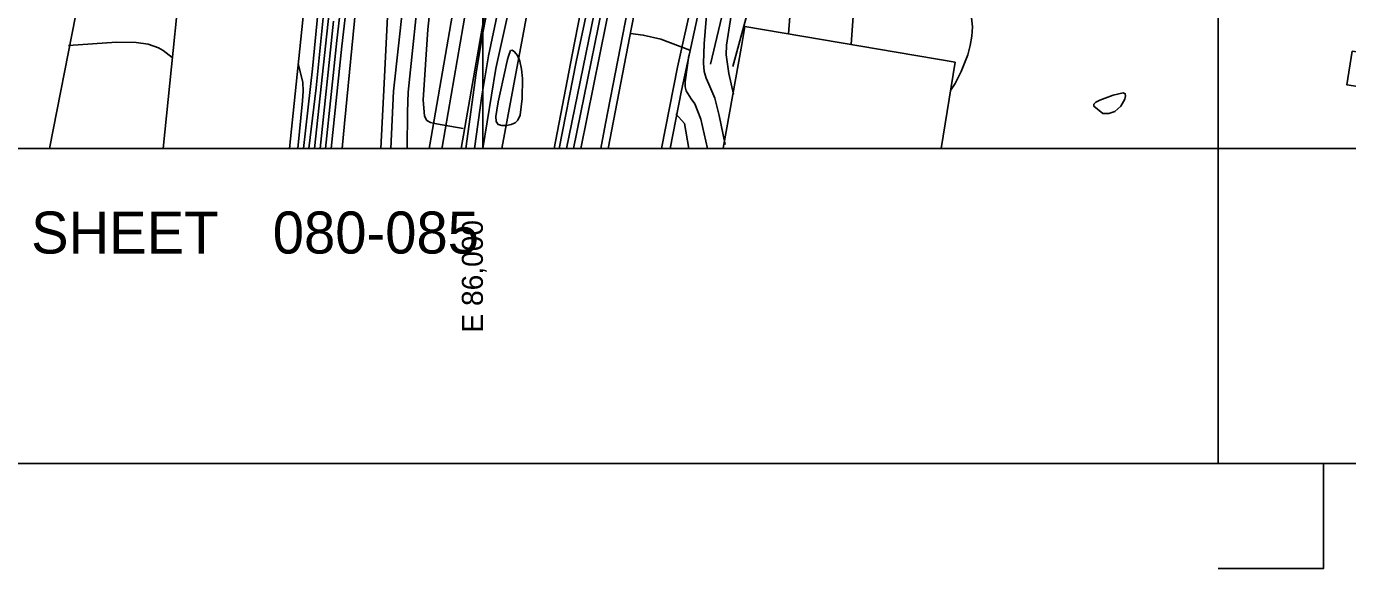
# Model space of a CAD drawing. Extents: x 79600 to 91800, y 75600 to 84400.
# Drawn here: x 85566 to 86823, y 75600 to 76116 of the extents above; entities that cross this region are included whole.
import ezdxf

# ---------------------------------------------------------------- set-up
doc = ezdxf.new("R2010")
doc.units = 0
for name, color, linetype in [('080-085$0$TI_BORDER', 7, 'Continuous'), ('080-085$0$TI_SHEET', 7, 'Continuous'), ('080-090$0$BLDG', 7, 'Continuous'), ('080-090$0$BRIDGE', 7, 'Continuous'), ('080-090$0$GRID', 7, 'Continuous'), ('080-090$0$INDEX', 7, 'Continuous'), ('080-090$0$INTER', 7, 'Continuous'), ('080-090$0$INTERSTATE', 7, 'Continuous'), ('080-090$0$ROAD', 7, 'Continuous'), ('080-090$0$TI_BORDER', 7, 'Continuous'), ('080-090$0$WALL', 7, 'Continuous')]:
    doc.layers.add(name, color=color, linetype=linetype)

msp = doc.modelspace()

# ---------------------------------------------------------------- linework, layer by layer
at = {"layer": '080-085$0$TI_BORDER'}
msp.add_lwpolyline([(79700, 80300), (86700, 80300), (86700, 75700), (79700, 75700)], close=True, dxfattribs=at)
at = {"layer": '080-085$0$TI_SHEET'}
msp.add_lwpolyline([(86800, 75700), (86800, 75600), (86700, 75600)], dxfattribs=at)
at = {"layer": '080-090$0$BLDG'}
for points in [[(85695.6, 76000), (85718.1, 76221.3), (85837.4, 76208.4), (85815.9, 76000)], [(85358.1, 76000), (85392.2, 76170.4), (85612.5, 76127.6), (85587.5, 76000)], [(86228.7, 76000.3), (86246.5, 76099.1), (86249.4, 76116.2), (86449.4, 76082.2), (86436.3, 76000)]]:
    msp.add_lwpolyline(points, dxfattribs=at)
msp.add_lwpolyline([(86827.4, 76092.8), (86867, 76086.7), (86862.1, 76054.6), (86822.5, 76060.6)], close=True, dxfattribs=at)
at = {"layer": '080-090$0$BRIDGE'}
for p, q in [((86145.8, 76172.8), (86116.8, 76023.7)), ((86209.4, 76148.7), (86188.9, 76055.3)), ((86188.9, 76055.3), (86178.3, 76000)), ((86116.8, 76023.7), (86112.2, 76000))]:
    msp.add_line(p, q, dxfattribs=at)
at = {"layer": '080-090$0$GRID'}
for p, q in [((86000, 80000), (86000, 76000)), ((90000, 76000), (85000, 76000))]:
    msp.add_line(p, q, dxfattribs=at)
at = {"layer": '080-090$0$INDEX'}
for points in [[(85927.8, 76000), (85928.3, 76034.8), (85929, 76053.7), (85940.5, 76166.4), (85942.9, 76204.7), (85944, 76214.5), (85946, 76224.2), (85952.3, 76242.8), (85964.5, 76269.2), (85970.7, 76287.2), (85974.6, 76305.9), (85979.2, 76352.9), (85985.2, 76393.6), (85995.7, 76517.2), (85998, 76546), (86001.9, 76573.1), (86010.6, 76615.9), (86033, 76705.4), (86037, 76723.4), (86038.8, 76748.9)], [(86093.2, 76000), (86135.3, 76209.3), (86140.8, 76236), (86143.9, 76254.4), (86147.6, 76303), (86150.1, 76322.3), (86178.9, 76480.4), (86187.7, 76517), (86195.1, 76545.1), (86212.3, 76599.8), (86215.3, 76608.6), (86218.8, 76616.1), (86223.1, 76621.8), (86233.7, 76630.3)], [(86230.7, 76003.8), (86225, 76031.4), (86220.7, 76047.9), (86215.2, 76061.3), (86212.6, 76067), (86210.7, 76073.4), (86209.9, 76081.2), (86210.7, 76099.7), (86213.9, 76138.6), (86216.4, 76157.4), (86223.2, 76185.1), (86231.3, 76213.4), (86243.4, 76250.4), (86253.2, 76278), (86269, 76313.3), (86276.5, 76331.1), (86282.5, 76349.4), (86292, 76393.6)], [(85991.9, 76000), (85999, 76050.2), (86005.5, 76088.4), (86029.4, 76202.5)], [(85839.7, 76000), (85860.2, 76189.1)]]:
    msp.add_lwpolyline(points, dxfattribs=at)
at = {"layer": '080-090$0$INTER'}
msp.add_line((85699.1, 76000), (85699.1, 76000), dxfattribs=at)
for points in [[(86136.6, 76835.2), (86135.6, 76809.7), (86134.3, 76791.6), (86112.5, 76652.2), (86066.7, 76407.8), (86054.2, 76342.6), (86048.2, 76314.1), (86025.3, 76231.1), (86017.9, 76203.3), (86000.1, 76110.1), (85993.6, 76072.1), (85983.9, 76000)], [(86238.3, 76654.5), (86225.3, 76647.6), (86213.2, 76641.1), (86207.8, 76637.2), (86203.4, 76632.2), (86200, 76625.5), (86190.7, 76590.4), (86167.9, 76488.3), (86139.6, 76349.9), (86130.4, 76304.6), (86128.6, 76296.7), (86126, 76290.4), (86121.8, 76286.9), (86115.6, 76287.2), (86108, 76290.3), (86100.1, 76295.3), (86092.7, 76300.9), (86086.3, 76307.1), (86072.9, 76326.3), (86070.1, 76328.1), (86067.7, 76324.9), (86018.7, 76104.6), (86012.3, 76076.2), (86000.1, 76000)], [(86237.2, 76648.5), (86227.4, 76643.3), (86217.1, 76637.7), (86212, 76634), (86207.6, 76629), (86204.2, 76622.3), (86194.3, 76587.4), (86174.3, 76502.5), (86128.4, 76268.5), (86088.7, 76082.6), (86072.7, 76000)], [(86079.6, 76000), (86126.9, 76231.2), (86138.9, 76305), (86170.5, 76470.3), (86178.4, 76506.3), (86194, 76569.5), (86201.3, 76596.9), (86205.9, 76613), (86208.3, 76619.8), (86211.5, 76625.6), (86215.8, 76630.2), (86236, 76642.5)], [(86086.4, 76000), (86123.3, 76182.4), (86133, 76229.4), (86138.5, 76258.2), (86142.8, 76296.9), (86146.7, 76325.7), (86174.8, 76474.7), (86180.6, 76501.8), (86192.3, 76548.3), (86208.1, 76602.5), (86210.9, 76611.2), (86214.6, 76618.8), (86219.2, 76624.9), (86234.8, 76636.5)], [(85912.3, 76000), (85915, 76054.5), (85928.3, 76175.7), (85929.8, 76194.7), (85931.7, 76213.9), (85933.5, 76223.3), (85936.3, 76232.4), (85944.4, 76249.5), (85954.4, 76265.6), (85959.2, 76273.9), (85963.3, 76282.6), (85966.5, 76291.6), (85970.6, 76310.1), (85973.5, 76347.2), (85979.8, 76389.5), (85983.3, 76419.8), (85989.9, 76518.4), (85991.3, 76537.6), (85993.4, 76556.3), (85996, 76571.5)], [(85981.1, 76019.2), (85955.8, 76023.5), (85950.3, 76024.7), (85946.6, 76026.8), (85944.4, 76030.9), (85943.2, 76046.5), (85947.6, 76113.2), (85953.6, 76170.7), (85955.1, 76199.6), (85956.6, 76218.8), (85960.5, 76237.7), (85969.7, 76265.2), (85975.2, 76283.7), (85979, 76303), (85991.2, 76403.1), (85992.3, 76414.8)], [(85834.5, 76000), (85841.2, 76057.7), (85852.6, 76172.5), (85854.4, 76191.5), (85855.5, 76208.9), (85855.4, 76215.6), (85854.4, 76220.2), (85852.1, 76223.1), (85847.9, 76224.8), (85805.9, 76228.5), (85767.4, 76233.9), (85720.1, 76239.3), (85686.8, 76238.6), (85681.3, 76238.4), (85673.4, 76239.8), (85670, 76241.9), (85666.9, 76245.5), (85664.7, 76250.8), (85663.5, 76258), (85663.3, 76266.5), (85664.2, 76275.4), (85671.2, 76300.1)], [(85829.3, 76000), (85837.9, 76075.8), (85846.6, 76168.3), (85848.1, 76186.6), (85848.5, 76194.9), (85848.3, 76201.7), (85847.4, 76206.1), (85845.5, 76207.7), (85837.1, 76205.2)], [(85855.5, 76000), (85865.9, 76097.4), (85871.1, 76144.1)], [(86290.8, 76109.2), (86294.1, 76149.9)], [(85850.2, 76000), (85861.1, 76102.7), (85865.4, 76141.5)], [(86352.9, 76130.6), (86350.7, 76099)], [(85845, 76000), (85857.8, 76121.3)], [(86238.7, 76051.8), (86234.2, 76071.3), (86231.6, 76089.1), (86231.9, 76098.5), (86236.4, 76126.9)], [(86445.1, 76055.1), (86449.6, 76062), (86455.3, 76073.2), (86461.5, 76089.3), (86463.9, 76098.1), (86465.4, 76107), (86465.9, 76115.8), (86465.2, 76124.3)], [(86140.5, 76109.5), (86152.6, 76108), (86169.4, 76104.2), (86197, 76093.5)], [(85704.4, 76086.6), (85695.8, 76093.3), (85691.4, 76096), (85681.4, 76099.3), (85670.1, 76100.9), (85651.4, 76101.3), (85605.6, 76098.1)], [(85823.8, 76000), (85828.3, 76045.4), (85828.8, 76054.6), (85828.6, 76062.8), (85824.2, 76080.9)], [(86195.9, 76088.6), (86192.7, 76063.4), (86192.6, 76058.8), (86193.4, 76054.9), (86198.4, 76047.4), (86201.7, 76042.4), (86207.4, 76028.1), (86213.9, 76000)], [(86196.1, 76000), (86192, 76023.8), (86183.6, 76033.1)]]:
    msp.add_lwpolyline(points, dxfattribs=at)
for points in [[(86023.5, 76084.7), (86016.4, 76053), (86014.7, 76044.3), (86013.3, 76036.6), (86012.4, 76030.4), (86012.7, 76025.8), (86014.4, 76023), (86017.9, 76021.8), (86022.4, 76021.9), (86026.9, 76022.8), (86030.6, 76024.4), (86033.4, 76027.1), (86035.4, 76031.7), (86037.5, 76047.6), (86037.6, 76066.8), (86036.8, 76075.6), (86035.3, 76083.1), (86032.9, 76088.6), (86030.2, 76092.1), (86027.9, 76093.6), (86026.3, 76093.3), (86024.3, 76087.9)], [(86591.2, 76033.3), (86595.7, 76033.4), (86601.6, 76035.4), (86607.2, 76040.3), (86611.1, 76047.1), (86611.8, 76050.1), (86611.4, 76052.1), (86609.5, 76052.9), (86599.8, 76050.8), (86587.3, 76046), (86583.4, 76044), (86581.6, 76042.1), (86581.6, 76040.3), (86590.1, 76033.4)]]:
    msp.add_lwpolyline(points, close=True, dxfattribs=at)
at = {"layer": '080-090$0$INTERSTATE'}
for p, q in [((86077.3, 76315.9), (86018, 76000)), ((86141.4, 76115.1), (86170, 76261.2)), ((85915.2, 76240.8), (85905.5, 76049.4)), ((86108, 76209.5), (86085.1, 76089.3)), ((85880.1, 76144.6), (85868.4, 76023.8)), ((86202.3, 76153.4), (86185.1, 76077.3)), ((85972.2, 76135.3), (85949.4, 76003.4)), ((85984, 76133.2), (85961.2, 76001.3)), ((86119.2, 76000), (86141.4, 76115.1)), ((86085.1, 76089.3), (86067.9, 76000)), ((86185.1, 76077.3), (86169.9, 76000)), ((85905.5, 76049.4), (85902.9, 76000)), ((85868.4, 76023.8), (85866.1, 76000)), ((85949.4, 76003.4), (85948.8, 76000)), ((85961.2, 76001.3), (85960.9, 76000))]:
    msp.add_line(p, q, dxfattribs=at)
at = {"layer": '080-090$0$ROAD'}
for p, q in [((86237.9, 76078.2), (86271.3, 76200)), ((86234, 76153.7), (86216.7, 76080.3))]:
    msp.add_line(p, q, dxfattribs=at)
at = {"layer": '080-090$0$TI_BORDER'}
msp.add_lwpolyline([(84700, 80300), (91700, 80300), (91700, 75700), (84700, 75700)], close=True, dxfattribs=at)
at = {"layer": '080-090$0$WALL'}
msp.add_lwpolyline([(86093.4, 76651), (86005.3, 76149.4), (85979.2, 76000)], dxfattribs=at)

# ---------------------------------------------------------------- texts
at = {"layer": '080-085$0$TI_SHEET'}
for s, p in [('SHEET', (85570, 75900)), ('080-085', (85800, 75900))]:
    msp.add_text(s, height=40, dxfattribs=at).set_placement(p)
at = {"layer": '080-090$0$GRID'}
msp.add_text('E 86,000', height=20, rotation=90, dxfattribs=at).set_placement((86000, 75824.8))

doc.saveas('drawing.dxf')
